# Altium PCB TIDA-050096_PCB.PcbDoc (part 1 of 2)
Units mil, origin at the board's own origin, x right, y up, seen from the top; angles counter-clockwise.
Board outline 3810 x 5470 mil, 4 copper layers (Top Layer, Layer 1, Layer 2, Bottom Layer), stack 70.356 mil thick; 143 components, 52 nets, 310 pads, 92 vias.
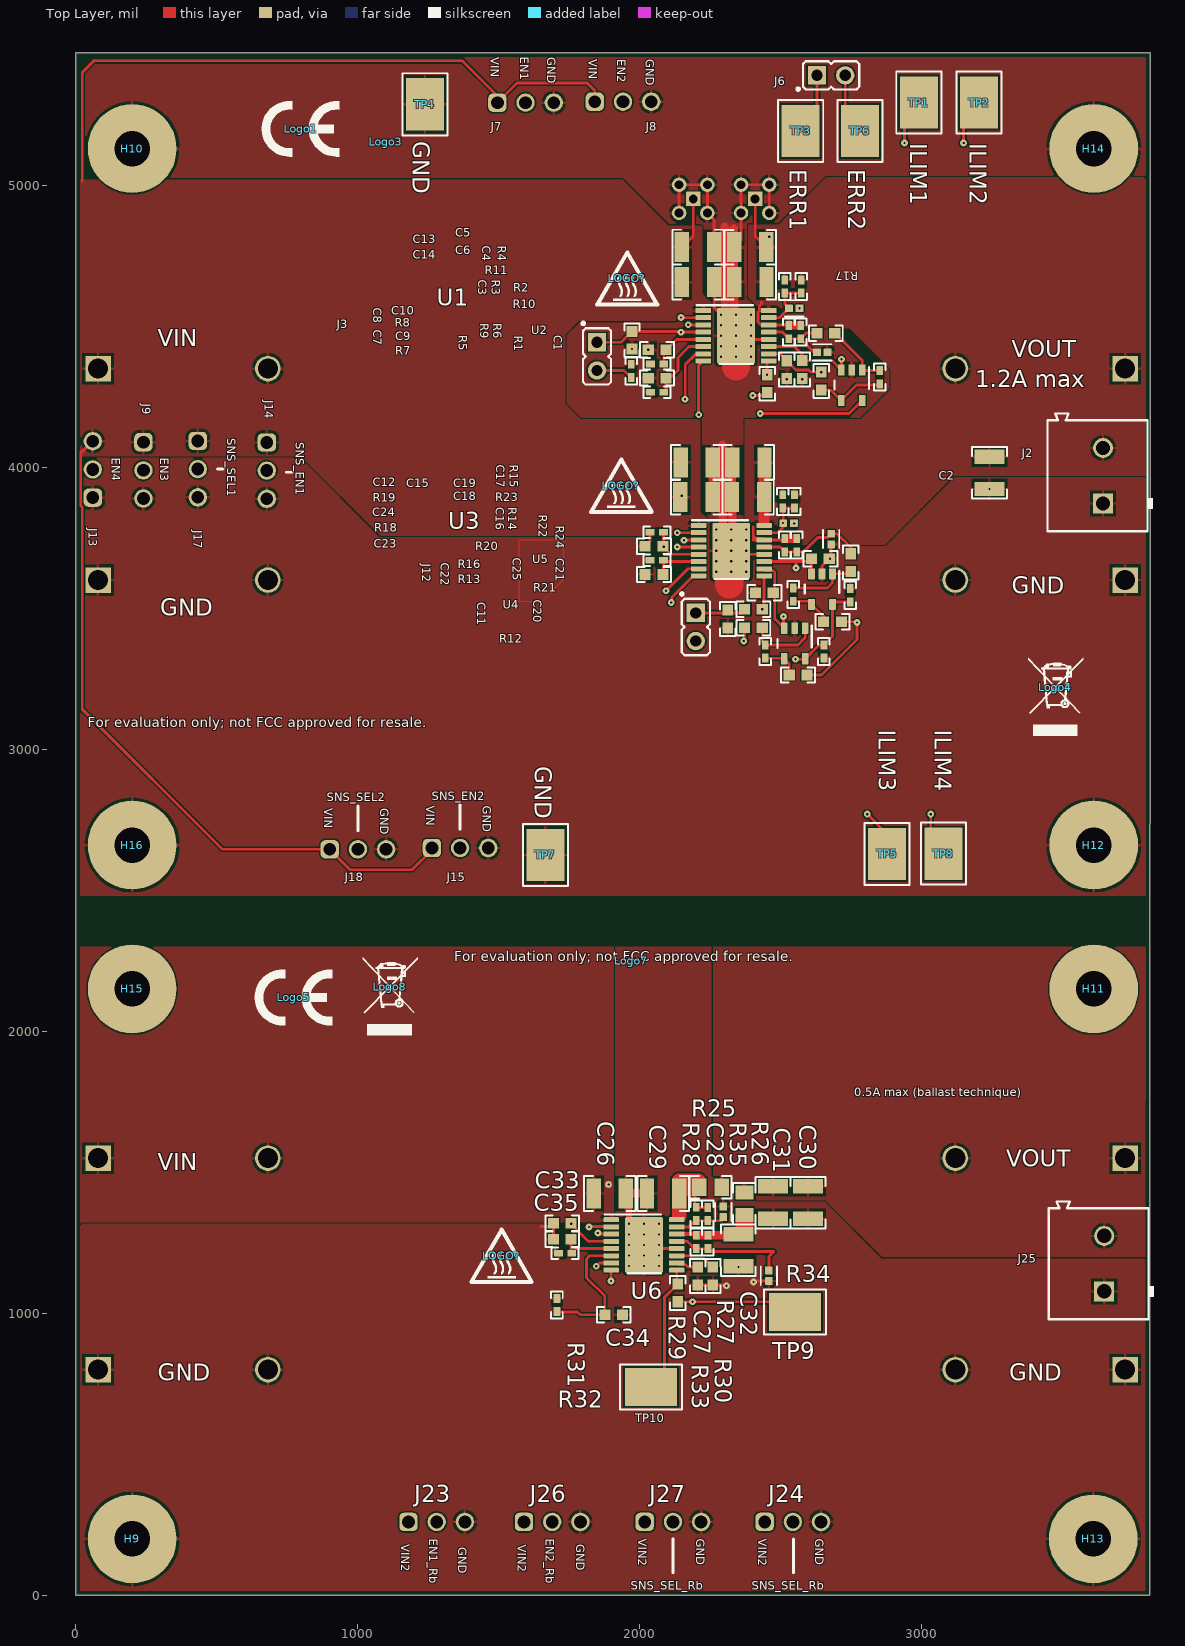
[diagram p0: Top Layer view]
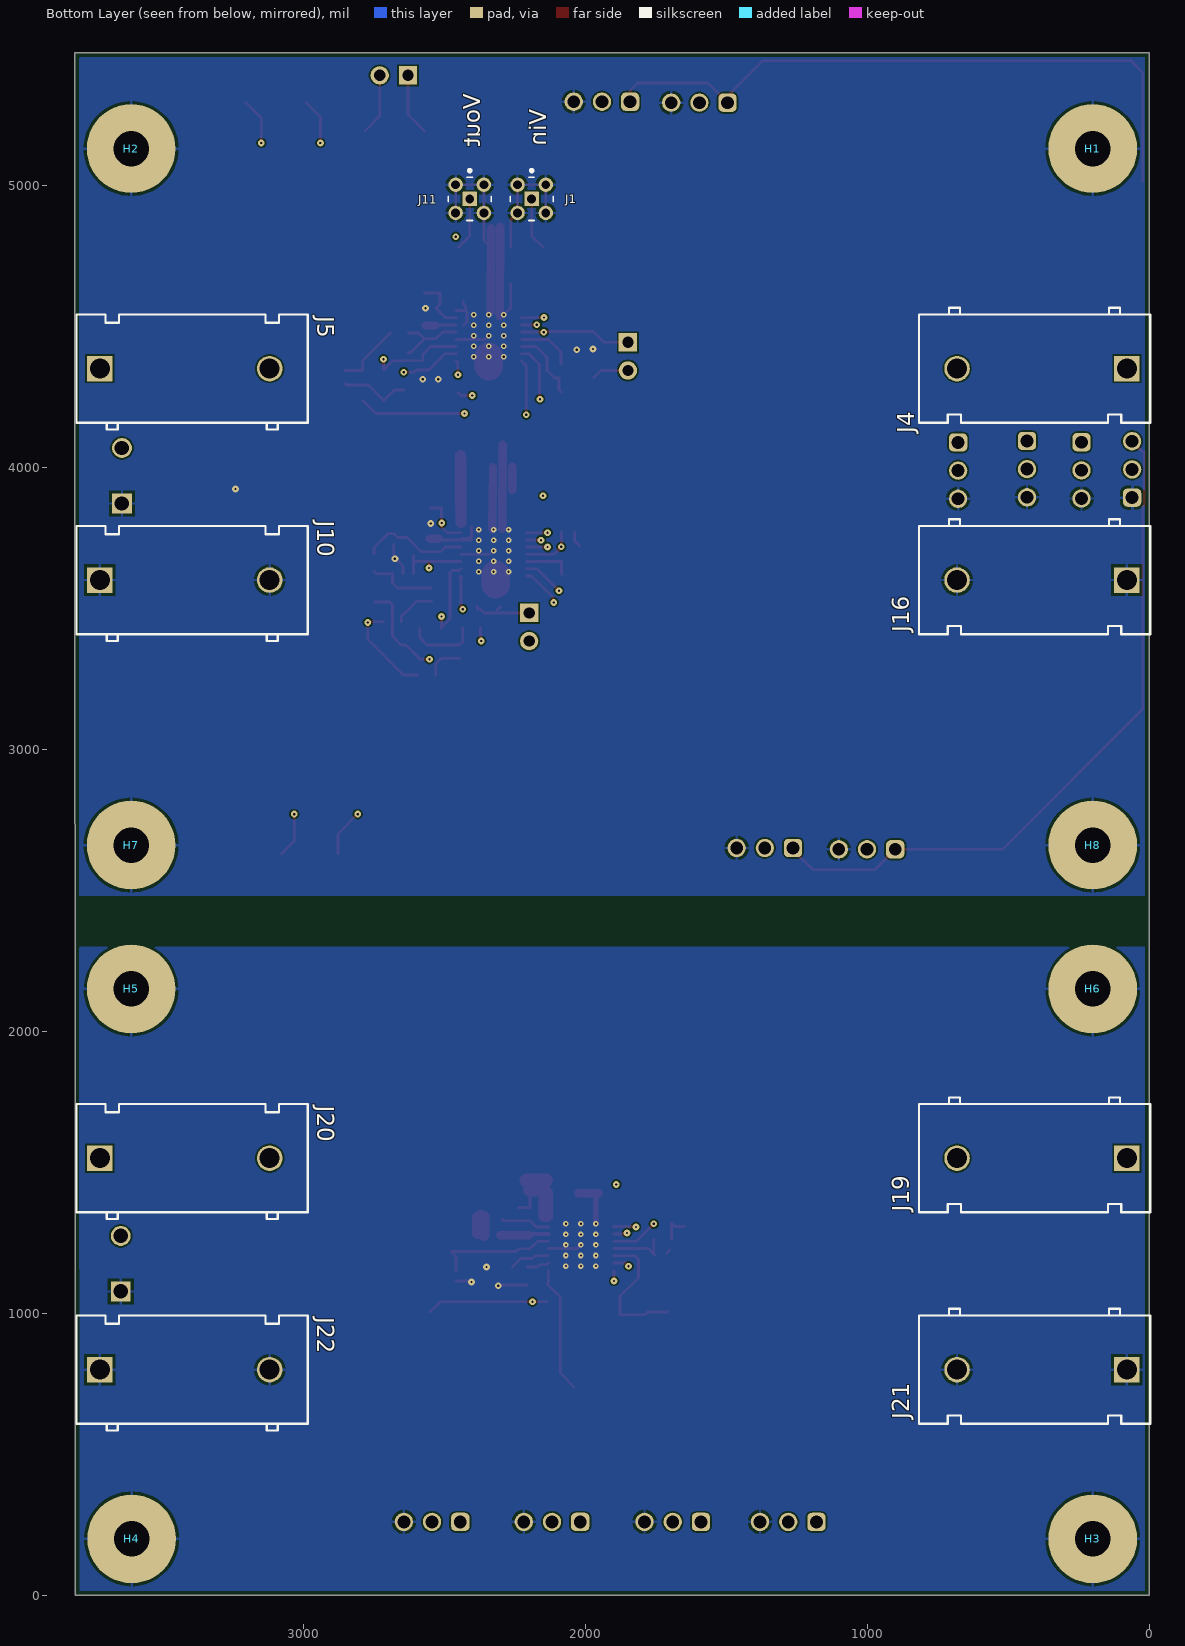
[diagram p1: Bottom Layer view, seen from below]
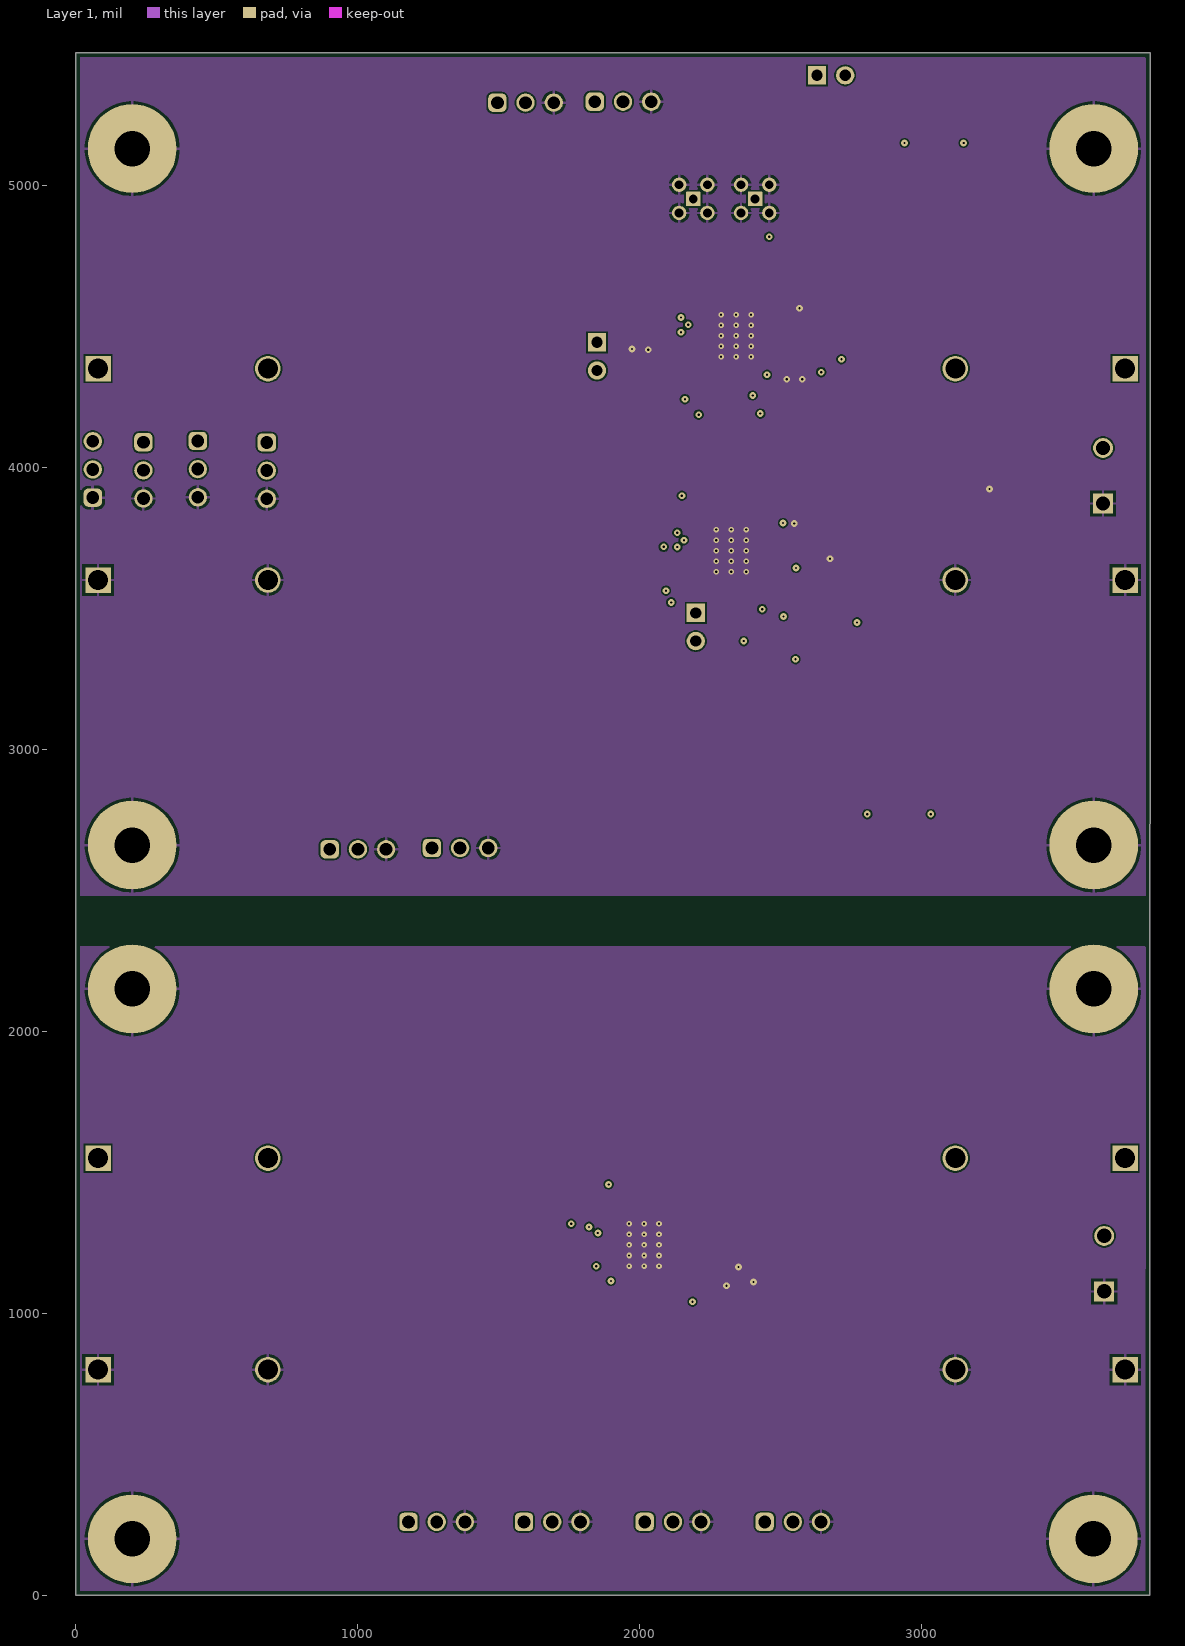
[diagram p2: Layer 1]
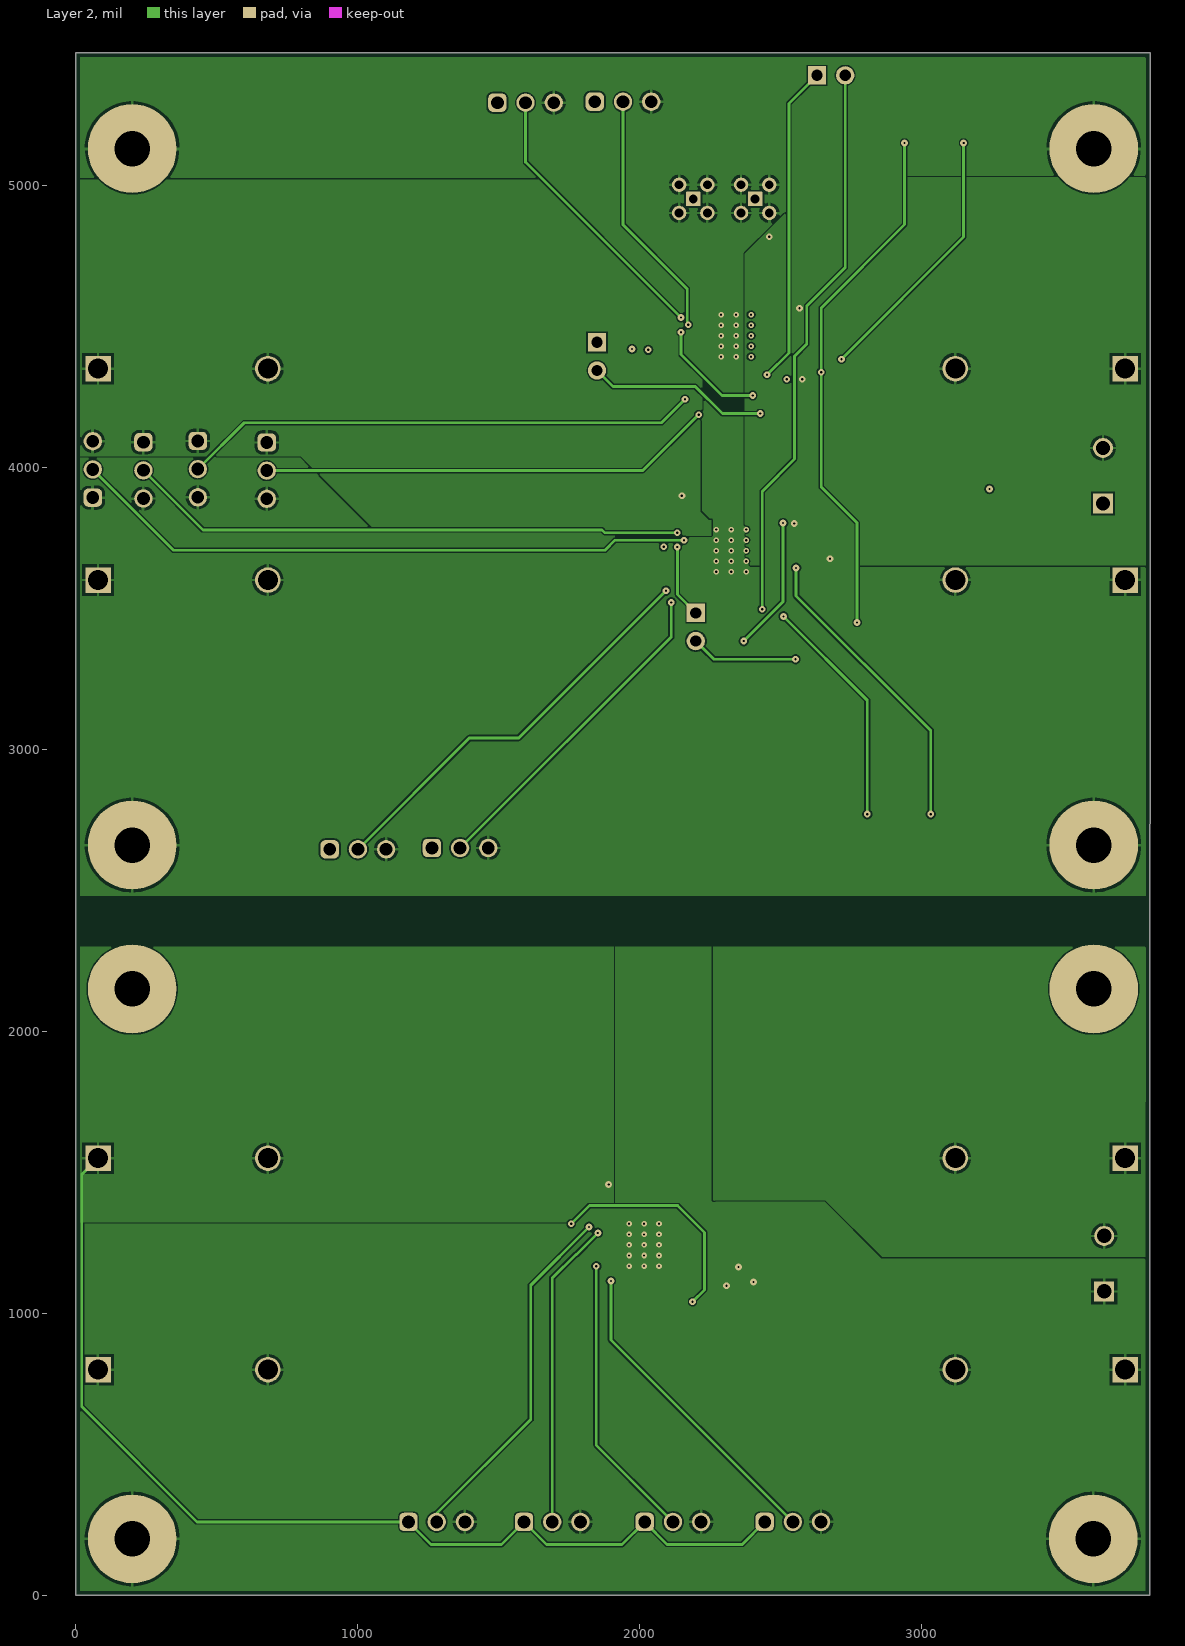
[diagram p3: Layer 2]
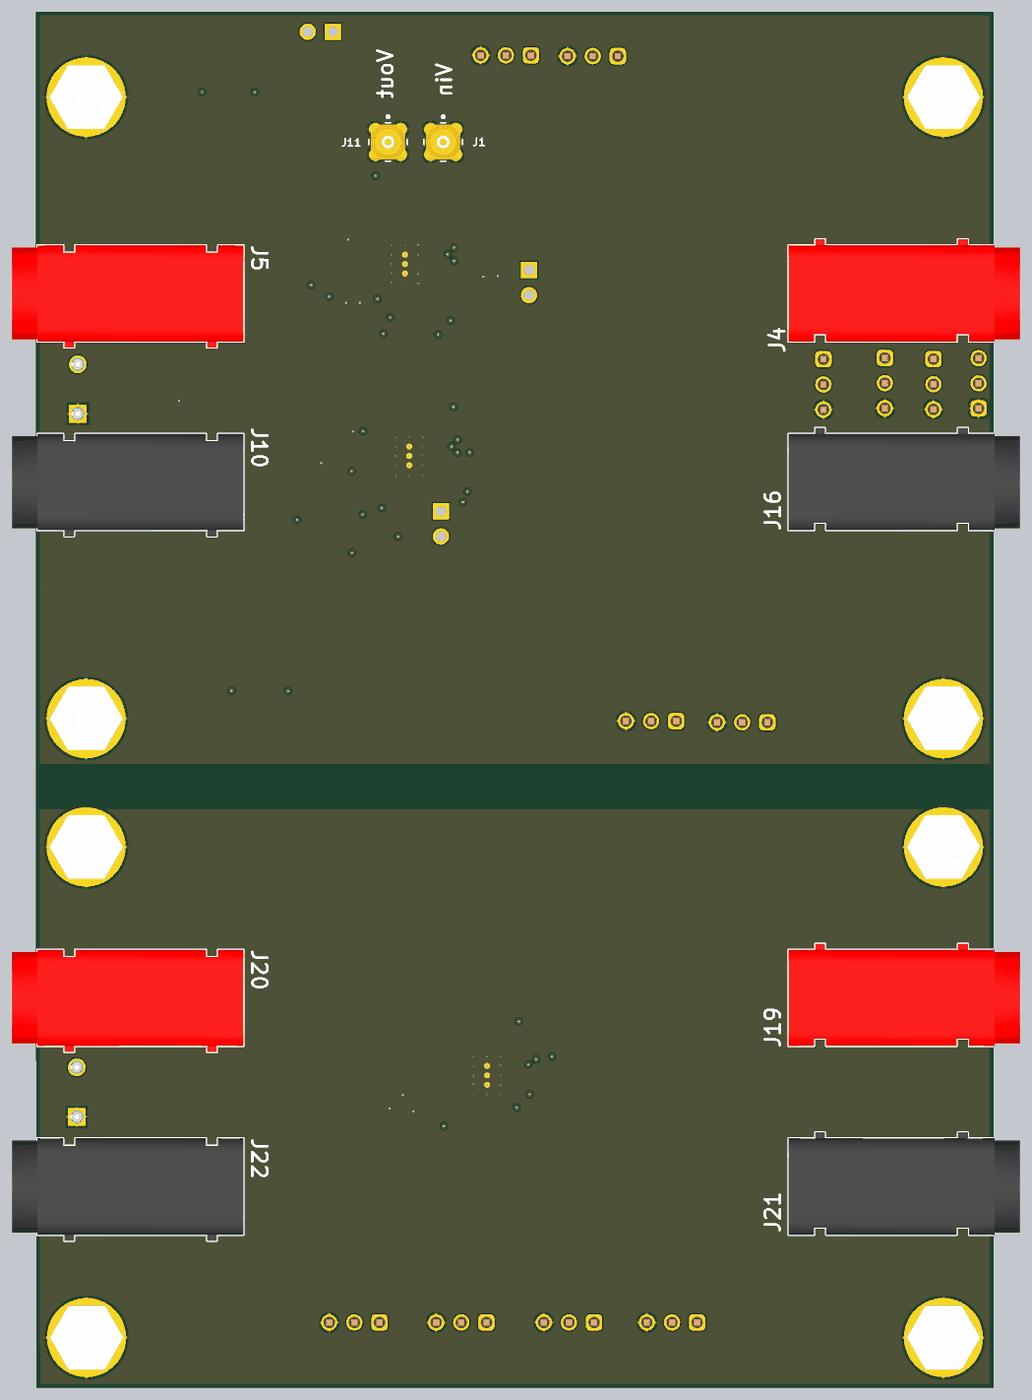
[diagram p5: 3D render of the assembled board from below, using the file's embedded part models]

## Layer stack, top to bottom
Top Solder: solder mask 0.4, Solder Resist, Dk 3.5
Top Layer: signal copper 1.4
Dielectric 1: prepreg 2.8, PP-006, Dk 4.1
Layer 1: signal copper 1.378
Dielectric1: core 59.2, FR-4, Dk 4.8
Layer 2: signal copper 1.378
Dielectric 2: prepreg 2.8, PP-006, Dk 4.1
Bottom Layer: signal copper 1.4
Bottom Solder: solder mask 0.4, Solder Resist, Dk 3.5

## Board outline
0,0 3808.27,0 3810,5470 0,5470

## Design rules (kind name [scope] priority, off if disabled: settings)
AcuteAngle [All] p1: minimum=4.50000000000000E+0001 checktracksonly=FALSE
AssemblyTestPointUsage [All] p1: valid=2
BoardOutlineClearance BoardOutlineClearance_MountingHoles [OnCopper and InComponentClass('Mounting Holes')] p1: gap=40 ignorepadtopadclearanceinfootprint=FALSE
BoardOutlineClearance BoardOutlineClearance_Poly [OnCopper and IsPoly] p2: gap=15 ignorepadtopadclearanceinfootprint=FALSE
BoardOutlineClearance [OnCopper and Not InComponentClass('Logo') and not InComponentClass('FiducialMark') and not InRegion(1000,500,4000,800) and not InPoly] p3: gap=15 ignorepadtopadclearanceinfootprint=FALSE
Clearance Clearance_Keepouts [((IsTrack Or IsArc) And Not InPoly) And IsFree and IsKeepOut vs ((IsTrack Or IsArc) And Not InPoly) And IsFree and IsKeepOut] p1: gap=0 ignorepadtopadclearanceinfootprint=FALSE
Clearance Clearance_Poly [InPolygon] p2: gap=5.63 ignorepadtopadclearanceinfootprint=FALSE except(0: Arc-Hole Track-Hole SMDPad-Hole THPad-Hole Via-Hole Fill-Hole Poly-Hole Region-Hole Text-Hole)
Clearance [Not InComponentClass('FiducialMark')] p3: gap=5.63 ignorepadtopadclearanceinfootprint=TRUE except(0: Arc-Hole Track-Hole SMDPad-Hole THPad-Hole Via-Hole Fill-Hole Poly-Hole Region-Hole Text-Hole)
ComponentClearance ComponentClearance_MountingHoles_FiducialMarks [InComponentClass('Mounting Holes') vs InComponentClass('FiducialMark')] p1: gap=50 collisioncheckmode=3 verticalgap=10 showdistances=FALSE
ComponentClearance ComponentClearance_Shunt [InComponentClass('Header') vs InComponentClass('Shunt')] p2: gap=0 collisioncheckmode=3 verticalgap=0 showdistances=FALSE
ComponentClearance ComponentClearance_NetTie [IsNetTieComponent] p3: gap=0 collisioncheckmode=3 verticalgap=10 showdistances=FALSE
ComponentClearance ComponentClearance_Logo [InComponentClass('Logo')] p4: gap=50 collisioncheckmode=3 verticalgap=10 showdistances=FALSE
ComponentClearance ComponentClearance_ScrewToNut [(HasFootprint('NY PMS 440 0025 PH')) vs (HasFootprint('Keystone_1902C'))] p5: gap=5 collisioncheckmode=3 verticalgap=10 showdistances=FALSE
ComponentClearance ComponentClearance_MountingHoles_Bumpon [InComponentClass('Mounting Holes') vs HasFootprint('Bumpon_SJ5003Transparent')] p6: gap=0 collisioncheckmode=3 verticalgap=0 showdistances=FALSE
ComponentClearance ComponentClearance_MountingHoles [InComponentClass('Mounting Holes')] p7: gap=250 collisioncheckmode=3 verticalgap=100000 showdistances=FALSE
ComponentClearance ComponentClearance_SmallPassives [HasFootprint('0201*') or HasFootprint('0402*') or HasFootprint('0508') or HasFootprint('0603*') or HasFootprint('0612') or HasFootprint('0805*') or HasFootprint('0815*') or HasFootprint('0830*') or HasFootprint('1206*') or HasFootprint('1210*') or HasFootprint('1808*') or HasFootprint('1812*') or HasFootprint('1825*') or HasFootprint('2010*') or HasFootprint('2220*') or HasFootprint('2225*') or HasFootprint('2512*') or HasFootprint('2728*') or HasFootprint('3518*') vs HasFootprint('0201*') or HasFootprint('0402*') or HasFootprint('0508') or HasFootprint('0603*') or HasFootprint('0612') or HasFootprint('0805*') or HasFootprint('0815*') or HasFootprint('0830*') or HasFootprint('1206*') or HasFootprint('1210*') or HasFootprint('1808*') or HasFootprint('1812*') or HasFootprint('1825*') or HasFootprint('2010*') or HasFootprint('2220*') or HasFootprint('2225*') or HasFootprint('2512*') or HasFootprint('2728*') or HasFootprint('3518*')] p8: gap=14.96 collisioncheckmode=3 verticalgap=10 showdistances=FALSE
ComponentClearance ComponentClearance_THtoSMT [IsThruComponent vs IsSMTComponent] p9: gap=40 collisioncheckmode=3 verticalgap=30 showdistances=FALSE
ComponentClearance ComponentClearance_THtoTH [IsThruComponent vs IsThruComponent] p10: gap=30 collisioncheckmode=3 verticalgap=30 showdistances=FALSE
ComponentClearance ComponentClearance_Bumpon [HasFootprint('Keystone_1902C') vs HasFootprint('Bumpon_SJ5003Transparent')] p11: gap=0 collisioncheckmode=3 verticalgap=0 showdistances=FALSE
ComponentClearance [All] p12: gap=30 collisioncheckmode=3 verticalgap=10 showdistances=FALSE
DiffPairsRouting [All] p1: maxlimit=100 minlimit=10 mostfreqgap=10 toplayer_minwidth=15 toplayer_maxwidth=15 toplayer_prefwidth=15 midlayer1_minwidth=15 midlayer1_maxwidth=15 midlayer1_prefwidth=15 midlayer2_minwidth=15 midlayer2_maxwidth=15 midlayer2_prefwidth=15 bottomlayer_minwidth=15 bottomlayer_maxwidth=15 bottomlayer_prefwidth=15 maxuncoupledlength=1000
FabricationTestPointUsage TestPointUsage [All] p1: valid=2 allowmultiple=FALSE
FabricationTestpoint Testpoint [All] p1: side=3 testpointundercomponent=TRUE minsize=40 maxsize=100 preferedsize=60 minholesize=0 maxholesize=40 preferedholesize=32 testpointgrid=1 allowsidetop=TRUE allowsidebottom=TRUE usegrid=TRUE gridtolerance=0.01
FanoutControl Fanout_LCC [IsLCC] p1: bgadir=Out bgaviamode=Centered fanoutstyle=Auto fanoutdirection=Alternating viagrid=1 // Fanout_LCC (Default Rule)
FanoutControl Fanout_BGA [IsBGA] p2: bgadir=Out bgaviamode=Centered fanoutstyle=Auto fanoutdirection=Alternating viagrid=1 // Fanout_BGA (Default Rule)
FanoutControl Fanout_Default [All] p4: bgadir=Out bgaviamode=Centered fanoutstyle=Auto fanoutdirection=Alternating viagrid=1 // Fanout_Default (Default Rule)
FanoutControl Fanout_Small [(CompPinCount < 5)] p5: bgadir=Out bgaviamode=Centered fanoutstyle=Auto fanoutdirection=OutThenIn viagrid=1 // Fanout_Small (Default Rule)
HoleSize [All] p1: absolutevalues=TRUE maxlimit=251 minlimit=6 maxpercent=80.000 minpercent=20.000
HoleToHoleClearance [All] p1: gap=10 allowstackedmicrovias=FALSE
MinimumAnnularRing MinimumAnnularRing_ThermalPadVias [IsVia and InAnyComponent] p1: minimumring=5
MinimumAnnularRing [All] p2: minimumring=5
MinimumSolderMaskSliver MinimumSolderMaskSliver_Logo [InComponentClass('Logo') vs InComponentClass('Logo')] p1: minsoldermaskwidth=0.7
MinimumSolderMaskSliver [All] p2: minsoldermaskwidth=3.94
PlaneConnect [All] p1: planeconnectstyle=Relief reliefexpansion=10 reliefentries=4 reliefconductorwidth=10 reliefairgap=10
PolygonConnect [All] p1: thpad.connectstyle=Relief thpad.reliefconductorwidth=10 thpad.reliefentries=4 thpad.polygonreliefangle="90 Angle" thpad.airgapwidth=10 smdpad.connectstyle=Relief smdpad.reliefconductorwidth=10 smdpad.reliefentries=4 smdpad.polygonreliefangle="90 Angle" smdpad.airgapwidth=10 via.connectstyle=Direct via.reliefconductorwidth=10 via.reliefentries=4 via.polygonreliefangle="90 Angle" via.airgapwidth=10
RoutingVias ThermalPadVias [IsVia and InAnyComponent] p1: holewidth=7 width=15 viastyle="Through Hole" minholewidth=7 minwidth=15 maxholewidth=12.99 maxwidth=23.62
RoutingVias [All] p2: holewidth=7 width=15 viastyle="Through Hole" minholewidth=7 minwidth=15 maxholewidth=40 maxwidth=65
SilkToBoardRegionClearance [Not ((IsComment or IsDesignator) And (Hide <> 'False')) and not InRegion(1000,500,4000,800)] p1:
SilkToSilkClearance SilkToSilkClearance_Pb-FreeLogo [(HasFootprint('Pb-Free_Overlay_Medium') OR HasFootprint('Pb-Free_Overlay_Small')) vs (HasFootprint('Pb-Free_Overlay_Medium') OR HasFootprint('Pb-Free_Overlay_Small'))] p1: silktosilkclearance=0
SilkToSilkClearance [All] p2: silktosilkclearance=4
SilkToSolderMaskClearance SilkToComponentPadClearance [(IsPad or IsFill or IsRegion) and InAnycomponent] p1: minsilkscreentomaskgap=5 clearancetoexposedcopper=TRUE
SilkToSolderMaskClearance "Silk to Solder Mask Opening" [All] p2: minsilkscreentomaskgap=4 clearancetoexposedcopper=FALSE
SolderMaskExpansion [All] p1: expansion=1.97 istentingtop=FALSE
SupplyNets "Schematic Supply Nets_1" [InNet('GND2')] p1: voltage=0.000
SupplyNets "Schematic Supply Nets" [InNet('GND')] p2: voltage=0.000
Width [All] p1: maxlimit=100 minlimit=6 preferedwidth=10 checkconnectedcopper=TRUE
14 further rules are at their usual default settings.

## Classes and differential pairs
component class Parallel_TPS7B7702_Rb_CM_Load: C26 C27 C28 C29 C30 C31 C32 C33 C34 C35 C36 J19 J20 J21 J22 J23 J24 J25 J26 J27 R25 R26 R27 R28 R29 R30 R31 R32 R33 R34 R35 TP9 TP10 U6
component class Header: J3 J6 J7 J8 J9 J12 J13 J14 J15 J17 J18 J23 J24 J26 J27
component class "Mounting Holes": H9 H10 H11 H12 H13 H14 H15 H16
component class Hardware: H1 H2 H3 H4 H5 H6 H7 H8 H9 H10 H11 H12 H13 H14 H15 H16 Logo1 Logo3 Logo4 Logo5 Logo7 Logo8 LOGO? ZZ1 ZZ2 ZZ3 ZZ4 ZZ5
component class AssemblyNote: ZZ1 ZZ2 ZZ3 ZZ4 ZZ5

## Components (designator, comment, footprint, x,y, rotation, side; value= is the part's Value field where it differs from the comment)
C1 "04023C103JAT2A" 0402 2851.59,4319.57 r90 top value=0.01uF
C2 "GRM32ER71H106KA12L" 1210_270 3240,3980 r270 top value=10uF
C3 "04023C103JAT2A" 0402 2528.88,4479.31 r270 top value=0.01uF
C4 "04023C103JAT2A" 0402 2514.67,4641.17 r270 top value=0.01uF
C5 "GRM32ER71H106KA12L" 1210_270 2391.91,4780.44 r180 top value=10uF
C6 "GRM32ER71H106KA12L" 1210_270 2392.29,4656.83 r180 top value=10uF
C7 "C1005X7R1H104K050BE" 0402 1969.44,4341.79 r90 top value=0.1uF
C8 "GRM188R61H105KAALD" 0603 1972.39,4450.61 r90 top value=1uF
C9 "GRM188R61H105KAALD" 0603 2061.59,4316.51 r0 top value=1uF
C10 "GRM188R61H105KAALD" 0603 2061.59,4416.51 r0 top value=1uF
C11 "04023C103JAT2A" 0402 2444.63,3346.65 r90 top value=0.01uF
C12 "GRM32ER71H106KA12L" 1210_270 2201.83,4017.66 r0 top value=10uF
C13 "GRM32ER71H106KA12L" 1210_270 2206.59,4780.71 r0 top value=10uF
C14 "GRM32ER71H106KA12L" 1210_270 2206.59,4656.51 r0 top value=10uF
C15 "GRM32ER71H106KA12L" 1210_270 2201.38,3893.96 r0 top value=10uF
C16 "04023C103JAT2A" 0402 2513.56,3723.85 r270 top value=0.01uF
C17 "04023C103JAT2A" 0402 2507.47,3879.2 r270 top value=0.01uF
C18 "GRM32ER71H106KA12L" 1210_270 2385.14,4017.66 r180 top value=10uF
C19 "GRM32ER71H106KA12L" 1210_270 2383.95,3893.89 r180 top value=10uF
C20 "C1005X7R1H104K050BE" 0402 2653.07,3346.67 r270 top value=0.1uF
C21 "C1005X7R1H104K050BE" 0402 2746.41,3546.28 r90 top value=0.1uF
C22 "GRM188R61H105KAALD" 0603 2312.39,3462.15 r270 top value=1uF
C23 "GRM188R61H105KAALD" 0603 2050.45,3619.79 r0 top value=1uF
C24 "GRM188R61H105KAALD" 0603 2050.45,3719.79 r0 top value=1uF
C25 "04023C103JAT2A" 0402 2544.49,3548.38 r90 top value=0.01uF
C26 "GRM32ER71H106KA12L" 1210_270 1893.88,1424.91 r0 top value=10uF
C27 "04023C103JAT2A" 0402 2200.44,1253.07 r270 top value=0.01uF
C28 "04023C103JAT2A" 0402 2241.51,1351.94 r270 top value=0.01uF
C29 "GRM32ER71H106KA12L" 1210_270 2082.82,1424.59 r180 top value=10uF
C30 "GRM32ER71H106KA12L" 1210_270 2596.27,1392.54 r270 top value=10uF
C31 "GRM32ER71H106KA12L" 1210_270 2472.83,1392.54 r270 top value=10uF
C32 "GRM32ER71H106KA12L" 1210_270 2349.4,1223.11 r270 top value=10uF
C33 "GRM188R61H105KAALD" 0603 1725.12,1319.5 r180 top value=1uF
C34 "GRM188R61H105KAALD" 0603 1907.59,994.33 r180 top value=1uF
C35 "GRM188R61H105KAALD" 0603 1725.09,1262.19 r0 top value=1uF
H1 "1902C" Keystone_1902C 200,5130 r180 bottom locked
H2 "1902C" Keystone_1902C 3610,5130 r180 bottom locked
H3 "1902C" Keystone_1902C 200,200 r180 bottom locked
H4 "1902C" Keystone_1902C 3608.27,200 r180 bottom locked
H5 "1902C" Keystone_1902C 3610,2150 r180 bottom
H6 "1902C" Keystone_1902C 200,2150 r180 bottom
H7 "1902C" Keystone_1902C 3610,2660 r180 bottom
H8 "1902C" Keystone_1902C 200,2660 r180 bottom
H9 "NY PMS 440 0025 PH" "NY PMS 440 0025 PH" 200,200 r0 top locked
H10 "NY PMS 440 0025 PH" "NY PMS 440 0025 PH" 200,5130 r0 top locked
H11 "NY PMS 440 0025 PH" "NY PMS 440 0025 PH" 3610,2150 r0 top
H12 "NY PMS 440 0025 PH" "NY PMS 440 0025 PH" 3610,2660 r0 top
H13 "NY PMS 440 0025 PH" "NY PMS 440 0025 PH" 3608.27,200 r0 top locked
H14 "NY PMS 440 0025 PH" "NY PMS 440 0025 PH" 3610,5130 r0 top locked
H15 "NY PMS 440 0025 PH" "NY PMS 440 0025 PH" 200,2150 r0 top
H16 "NY PMS 440 0025 PH" "NY PMS 440 0025 PH" 200,2660 r0 top
J1 "RF12-07H-T-00-50-G" FP-RF12-07H-T-00-50-G_CONN_MMCX-MFG 2409.22,4951.97 r270 bottom
J2 "691 101 710 002" Wurth_691101710002 3642.74,3970 r90 top
J3 "PBC02SAAN" Sullins_PBC02SAAN 1848.44,4393.21 r0 top
J4 "571-0500" 571-0500 380,4350 r0 bottom
J5 "571-0500" 571-0500 3420,4350 r180 bottom
J6 "PBC02SAAN" Sullins_PBC02SAAN 2678.54,5390 r90 top
J7 "61300311121" WURTH_61300311121 1595,5293.09 r0 top
J8 "61300311121" WURTH_61300311121 1940.57,5296.49 r0 top
J9 "61300311121" WURTH_61300311121 239.68,3989.1 r270 top
J10 "571-0100" 571-0100 3420,3600 r180 bottom
J11 "RF12-07H-T-00-50-G" FP-RF12-07H-T-00-50-G_CONN_MMCX-MFG 2189.66,4951.97 r270 bottom
J12 "PBC02SAAN" Sullins_PBC02SAAN 2198.61,3433.65 r0 top
J13 "61300311121" WURTH_61300311121 60.33,3992.49 r90 top
J14 "61300311121" WURTH_61300311121 677.35,3988.19 r270 top
J15 "61300311121" WURTH_61300311121 1362.81,2650.02 r0 top
J16 "571-0100" 571-0100 380,3600 r0 bottom
J17 "61300311121" WURTH_61300311121 432.84,3993.49 r270 top
J18 "61300311121" WURTH_61300311121 1000.42,2645.17 r0 top
J19 "571-0500" 571-0500 380,1550 r0 bottom
J20 "571-0500" 571-0500 3420,1550 r180 bottom
J21 "571-0100" 571-0100 380,800 r0 bottom
J22 "571-0100" 571-0100 3420,800 r180 bottom
J23 "61300311121" WURTH_61300311121 1279.75,260 r0 top
J24 "61300311121" WURTH_61300311121 2542.93,260 r0 top
J25 "691 101 710 002" Wurth_691101710002 3646.99,1175.73 r90 top
J26 "61300311121" WURTH_61300311121 1689.47,260 r0 top
J27 "61300311121" WURTH_61300311121 2117.53,260 r0 top
Logo1 "CE Mark" CE_Mark_5mm 797.27,5200.04 r0 top
Logo3 "FCC disclaimer" FCC_disclaimer 1100,5155.19 r0 top
Logo4 "WEEE logo" WEEE_Minimum 3473.45,3220 r0 top
Logo5 "CE Mark" CE_Mark_5mm 772.4,2119.79 r0 top
Logo7 "FCC disclaimer" FCC_disclaimer 1970,2250 r0 top
Logo8 "WEEE logo" WEEE_Minimum 1112.72,2157.99 r0 top
LOGO? "CAUTION HOT SURFACE" IEC_HotSurface_Small 1510,1203.85 r0 top
LOGO? "CAUTION HOT SURFACE" IEC_HotSurface_Small 1934.78,3935.07 r0 top
LOGO? "CAUTION HOT SURFACE" IEC_HotSurface_Small 1955.78,4669.8 r0 top
R1 "RC0603FR-0710KL" 0603 2643.34,4305.79 r270 top value=10.0k
R2 "RC0603FR-07787RL" 0603 2659.84,4475.76 r180 top value=787
R3 "CRCW04027K15FKED" 0402 2570.36,4479.31 r270 top value=7.15k
R4 "CRCW04027K15FKED" 0402 2572.09,4641.17 r270 top value=7.15k
R5 "RC0603FR-0710KL" 0603 2451.59,4296.51 r90 top value=10.0k
R6 "RC0603FR-07787RL" 0603 2576.14,4346.65 r90 top value=787
R7 "CRCW0402732RFKED" 0402 2061.59,4266.51 r0 top value=732
R8 "CRCW0402732RFKED" 0402 2061.59,4366.51 r0 top value=732
R9 "RC0603FR-07787RL" 0603 2521.59,4346.51 r90 top value=787
R10 "RC0402FR-071KL" FP-RC0402FR-071KL_0402-IPC_A 2647.18,4407.46 r180 top value=1k
R11 "RC0402FR-071KL" FP-RC0402FR-071KL_0402-IPC_A 2547.72,4563.86 r180 top value=1k
R12 "RC0603FR-0710KL" 0603 2561.47,3263.45 r180 top value=10.0k
R13 "RC0603FR-07787RL" 0603 2402.69,3431.17 r180 top value=787
R14 "CRCW04027K15FKED" 0402 2556.49,3723.85 r270 top value=7.15k
R15 "CRCW04027K15FKED" 0402 2548.75,3879.2 r270 top value=7.15k
R16 "RC0603FR-0710KL" 0603 2402.69,3496.8 r0 top value=10.0k
R17 "RC0603FR-07787RL" 0603 2640.41,3675.85 r180 top value=787
R18 "CRCW0402732RFKED" 0402 2060.45,3669.79 r0 top value=732
R19 "CRCW0402732RFKED" 0402 2060.45,3769.79 r0 top value=732
R20 "RC0603FR-07787RL" 0603 2441.79,3555.46 r0 top value=787
R21 "RC0603FR-0710KL" 0603 2683.72,3452.35 r180 top value=10.0k
R22 "RC0402FR-071KL" FP-RC0402FR-071KL_0402-IPC_A 2678.54,3745.56 r90 top value=1k
R23 "RC0402FR-071KL" FP-RC0402FR-071KL_0402-IPC_A 2527.57,3801.76 r180 top value=1k
R24 "RC0603FR-07787RL" 0603 2748.75,3662.04 r90 top value=787
R25 "RC0805FR-071R33L" 0805_HV 2250.87,1446.94 r0 top value=1.33
R26 "RC0805FR-071R33L" 0805_HV 2371.02,1388.41 r90 top value=1.33
R27 "CRCW04027K15FKED" 0402 2241.76,1252.96 r270 top value=7.15k
R28 "CRCW04027K15FKED" 0402 2200.15,1352.05 r270 top value=7.15k
R29 "RC0603FR-0710KL" 0603 2135.09,1072.19 r90 top value=10.0k
R30 "RC0603FR-07787RL" 0603 2259.56,1132.29 r90 top value=787
R31 "CRCW0402732RFKED" 0402 1706.39,1029.17 r270 top value=732
R32 "CRCW0402732RFKED" 0402 1735.09,1212.19 r0 top value=732
R33 "RC0603FR-07787RL" 0603 2205.09,1132.19 r90 top value=787
R34 "RC0402FR-071KL" FP-RC0402FR-071KL_0402-IPC_A 2457.86,1133.21 r90 top value=1k
R35 "RC0402FR-071KL" FP-RC0402FR-071KL_0402-IPC_A 2296.17,1359.5 r270 top value=1k
TP1 "5016" Testpoint_Keystone_Compact 2989.51,5293.15 r90 top
TP2 "5016" Testpoint_Keystone_Compact 3203.19,5293.15 r270 top
TP3 "5016" Testpoint_Keystone_Compact 2570.64,5193.15 r90 top
TP4 "5016" Testpoint_Keystone_Compact 1238.14,5287.43 r90 top
TP5 "5016" Testpoint_Keystone_Compact 2876.88,2628.63 r270 top
TP6 "5016" Testpoint_Keystone_Compact 2780.64,5193.15 r270 top
TP7 "5016" Testpoint_Keystone_Compact 1665.27,2625.17 r90 top
TP8 "5016" Testpoint_Keystone_Compact 3076.88,2629.73 r90 top
TP9 "5016" Testpoint_Keystone_Compact 2550,1004.17 r0 top
TP10 "5016" Testpoint_Keystone_Compact 2039.58,738.95 r0 top
U1 "TPS7B7702QPWPRQ1" PWP0016J_N 2341.59,4466.51 r0 top
U2 "OPA388IDBVR" DBV0005A_N 2751.59,4291.53 r270 top
U3 "TPS7B7702QPWPRQ1" PWP0016J_N 2324.58,3704.16 r0 top
U4 "OPA388IDBVR" DBV0005A_N 2549.19,3375.14 r270 top
U5 "OPA388IDBVR" DBV0005A_N 2646.32,3568.07 r270 top
U6 "TPS7B7702QPWPRQ1" PWP0016J_N 2015.09,1242.19 r0 top
ZZ1 "This Assembly Note is for PCB labels only" AssemblyNoteLabel -395.71,7825.79 r0 top
ZZ2 "These assemblies are ESD sensitive, ESD precautions shall be observed." AssemblyNote -395.71,7716.91 r0 top
ZZ3 "These assemblies must be clean and free from flux and all contaminants. Use of no clean flux is not acceptable." AssemblyNote -395.71,7628.35 r0 top
ZZ4 "These assemblies must comply with workmanship standards IPC-A-610 Class 2, unless otherwise specified." AssemblyNote -395.71,7539.8 r0 top
ZZ5 "The tab route width shall be between 80 mils and 120 mils" AssemblyNote -400,7440 r0 top

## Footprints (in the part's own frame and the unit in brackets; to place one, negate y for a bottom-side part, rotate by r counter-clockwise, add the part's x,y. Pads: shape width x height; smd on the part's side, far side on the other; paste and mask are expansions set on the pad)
0402 [mm] "0402 from SM-752 data"
  rect 0.8x0.6 smd: 1(-0.6,0) 2(0.6,0)
  silkscreen extent -1.22,-0.52 1.22,0.52, body extent -0.55,-0.3 0.55,0.3, height 0.6
571-0100 [mm] "Deltron Emcon recommended land pattern 2003-10-13"
  rect 2.3x2.3 hole 1.8: 1(-7.65,0)
  round 2.3 hole 1.8: 2(7.65,0)
  silkscreen extent -9.74,-5.47 11.09,4.88, body extent -12.28,-5.47 11.09,4.88, height 12.41
571-0500 [mm] "Deltron Emcon recommended land pattern 2003-10-13"
  rect 2.3x2.3 hole 1.8: 1(-7.65,0)
  round 2.3 hole 1.8: 2(7.65,0)
  silkscreen extent -9.74,-5.47 11.09,4.88, body extent -12.28,-5.47 11.09,4.88, height 12.41
0603 [mm] "0603 from SM-752 data"
  rect 1x0.95 smd: 1(-0.8,0) 2(0.8,0)
  silkscreen extent -1.52,-0.69 1.52,0.69, body extent -0.87,-0.47 0.87,0.47, height 1
0805_HV [mil] "0805 with 30mil clearance between pads"
  rect 50x63 smd: 1(-40,0) 2(40,0)
  silkscreen extent -74,-40 74,40, body extent -43,-29 43,29, height 57
1210_270 [mm] "1210"
  rect 1.3x2.7 smd: 1(-1.45,0) 2(1.45,0)
  silkscreen extent -2.32,-1.57 2.32,1.57, body extent -1.7,-1.35 1.7,1.35, height 2.7
AssemblyNote [mil] "Assembly Note"
AssemblyNoteLabel [mil] "Assembly Note for PCB Labels"
CE_Mark_5mm [mil] "Minimum text height for CE Mark"
  silkscreen extent -138,-98 138,98
DBV0005A_N [mm] "SOT23, 5-Leads, Body 2.9x1.6mm, Pitch 0.95mm, Lead Span 2.8mm, IPC Medium Density"
  rrect17% 1x0.6 smd: 1(-1.375,0.95) 2(-1.375,0) 3(-1.375,-0.95) 4(1.375,-0.95) 5(1.375,0.95)
  silkscreen extent -1.63,-1.55 0.38,1.55, body extent -1.42,-1.46 1.42,1.46, height 1.09
FCC_disclaimer [mil]
FP-RC0402FR-071KL_0402-IPC_A [mil]
  rrect15% 28.16x26.48 smd paste+0 mask+0: 1(-18.84,0) 2(18.84,0)
  silkscreen extent -33,-29 33,29, body extent -41,-21 41,21, height 10
FP-RF12-07H-T-00-50-G_CONN_MMCX-MFG [mm]
  rrect8% 1.3x1.3 hole 0.8 paste-2539.97 mask+0: 1(0,0)
  round 1.3 hole 0.8 paste-2539.97 mask+0: 2(-1.27,1.27) 3(1.27,1.27) 4(-1.27,-1.27) 5(1.27,-1.27)
  silkscreen extent -2.67,-1.94 1.94,1.94, body extent -1.75,-1.75 1.75,1.75, height 5.26
IEC_HotSurface_Small [mil]
  silkscreen extent -107,-93 107,92
Keystone_1902C [mil] "Hex Standoff, 4-40 threaded, nylon"
  round 1 on Mech4: 0(0,0)
  body extent -145,-126 146,126, height 501
"NY PMS 440 0025 PH" [mm] "4-40 nylon screw and mounting hole"
  round 8 hole 3.2: 1(0,0)
  body extent -3.3,-3.3 3.3,3.3, height 2.69
PWP0016J_N [mm] "TSOP, 16-Leads, Body 5x4.4mm, Pitch 0.65mm, Exposed Pad, IPC Medium Density"
  rrect22% 1.4x0.45 smd: 1(-2.95,2.275) 2(-2.95,1.625) 3(-2.95,0.975) 4(-2.95,0.325) 5(-2.95,-0.325) 6(-2.95,-0.975) 7(-2.95,-1.625) 8(-2.95,-2.275) 9(2.95,-2.275) 10(2.95,-1.625) 11(2.95,-0.975) 12(2.95,-0.325) 13(2.95,0.325) 14(2.95,0.975) 15(2.95,1.625) 16(2.95,2.275)
  rrect6% 3.4x5 smd paste-1.7 mask-1.7: 17(0,0)
  rrect4% 2.46x3.55 on Top Solder: 17(0,0)
  rrect4% 2.46x3.55 on Top Paste: 17(0,0)
  silkscreen extent -3.55,-2.55 1.5,2.75, body extent -3.2,-2.5 3.2,2.5, height 1.13
Sullins_PBC02SAAN [mm] "Sullins 100mil, 1x2, 230 mil above insulator"
  rect 1.65x1.65 hole 1.016: 1(0,1.27)
  round 1.65 hole 1.016: 2(0,-1.27)
  silkscreen extent -1.37,-2.54 1.27,3.1, body extent -1.27,-2.54 1.27,2.54, height 8.38
Testpoint_Keystone_Compact [mil] "Compact SMT test point"
  rect 185x135 smd: 1(0,0)
  silkscreen extent -110,-80 110,80, body extent -75,-56 75,56, height 91
WEEE_Minimum [mil] "WEEElie bin"
  silkscreen extent -95,-172 99,104
WURTH_61300311121 [mm] "Header, 2.54mm, 3x1, TH"
  rrect50% 1.65x1.65 hole 1.15: 1(-2.54,0)
  round 1.65 hole 1.15: 2(0,0) 3(2.54,0)
  body extent -3.81,-1.27 3.81,1.27, height 8.54
Wurth_691101710002 [mm] "Terminal Block, 5 mm, 2x1, TH"
  rect 1.8x1.8 hole 1.3: 1(-2.5,0)
  round 1.8 hole 1.3: 2(2.5,0)
  silkscreen extent -5,-4.5 5.6,5, body extent -5.6,-4 5.6,5, height 12.5

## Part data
C1 C3 C4 C11 C16 C17 C25 C27 C28: library part CMP-0085568-1, "CAP, CERM, 0.01 µF, 25 V,+/- 5%, X7R, 0402", Cap_Case=0402, Manufacturer=AVX, TempCo=X7R, Tolerance_%=5%, Value2=25V, ValueDisplayed=0.01µF
C2 C5 C6 C12 C13 C14 C15 C18 C19 C26 C29 C30 C31 C32: library part CMP-0009226-3, "CAP, CERM, 10 uF, 50 V, +/- 10%, X7R, 1210", Cap_Case=1210, Manufacturer=MuRata, Supplier Part Number 1=490-6544-1-ND, TempCo=X7R, Tolerance_%=10%, Value1=Unknown, Value2=50V, ValueDisplayed=10uF
C7 C20 C21: library part CMP-0064946-2, "CAP, CERM, 0.1 uF, 50 V,+/- 10%, X7R, 0402", Cap_Case=0402, Manufacturer=TDK, Supplier Part Number 1=445-173610-1-ND, TempCo=X7R, Tolerance_%=10%, Value1=Unknown, Value2=50V, ValueDisplayed=0.1uF
C8 C9 C10 C22 C23 C24 C33 C34 C35: library part CMP-0007350-6, "CAP, CERM, 1 uF, 50 V, +/- 10%, X5R, 0603", Cap_Case=0603, Manufacturer=MuRata, Supplier Part Number 1=13T1194, TempCo=X5R, Tolerance_%=10%, Value1=Unknown, Value2=50V, ValueDisplayed=1uF
H1 H2 H3 H4 H5 H6 H7 H8: library part CMP-0003610-1, "Standoff, Hex, 0.5\"L #4-40 Nylon", Manufacturer=Keystone, Supplier Part Number 1=36-1902C-ND
H9 H10 H11 H12 H13 H14 H15 H16: library part CMP-0003617-1, "Machine Screw, Round, #4-40 x 1/4, Nylon, Philips panhead", Manufacturer="B&F Fastener Supply", Supplier Part Number 1=H542-ND
J1 J11: library part CMP-0096285-1, "MMCX Connector Jack, Female Socket 50Ohm Through Hole Solder", Dielectric Material=TEFLON, Digikey Part Number=2057-RF12-07H-T-00-50-G-ND, Manufacturer="Adam Tech", Operating Temperature Range=to
J2 J25: library part CMP-0054828-1, "Terminal Block, 5 mm, 2x1, Tin, TH", Manufacturer="Wurth Elektronik", Supplier Part Number 1=732-2026-ND
J3 J6 J12: library part CMP-0054566-1, "Header, 100mil, 2x1, Gold, TH", Color=Black, Current_A=3A, Manufacturer="Sullins Connector Solutions", Supplier Part Number 1=S1011E-02-ND, Voltage_V=1.8kV
J4 J5 J19 J20: library part CMP-0055393-3, "Standard Banana Jack, insulated, 10A, red", Manufacturer="DEM Manufacturing", Supplier Part Number 1=30M0087
J7 J8 J9 J13 J14 J15 J17 J18 J23 J24 J26 J27: library part CMP-0054796-4, "Header, 2.54 mm, 3x1, Gold, TH", Manufacturer="Wurth Elektronik", Supplier Part Number 1=732-5316-ND
J10 J16 J21 J22: library part CMP-0055389-3, "Standard Banana Jack, insulated, 10A, black", Manufacturer="DEM Manufacturing", Supplier Part Number 1=45M6896
Logo1 Logo5: library part CMP-0074844-1
Logo3 Logo7: library part CMP-0074847-1, "FCC_disclaimer"
Logo4 Logo8: library part CMP-0074769-1
LOGO? LOGO? LOGO?: library part CMP-0074837-1, "IEC 61010-1 Hot Surface Warning"
R1 R5 R12 R16 R21 R29: library part CMP-0022746-5, "RES, 10.0 k, 1%, 0.1 W, 0603", Manufacturer=Yageo, Power_W=100mW, Supplier Part Number 1=311-10.0KHRCT-ND, TempCo="100 ppm/C", Tolerance_%=1%, Value2=0.1W, Value_Code=10k0, ValueDisplayed=10.0k
R2 R6 R9 R13 R17 R20 R24 R30 R33: library part CMP-0023274-5, "RES, 787, 1%, 0.1 W, 0603", Manufacturer=Yageo, Power_W=100mW, Supplier Part Number 1=311-787HRCT-ND, TempCo="100 ppm/C", Tolerance_%=1%, Value2=0.1W, Value_Code=787R, ValueDisplayed=787
R3 R4 R14 R15 R27 R28: library part CMP-0026553-2, "RES, 7.15 k, 1%, 0.063 W, AEC-Q200 Grade 0, 0402", Manufacturer=Vishay-Dale, Power_W=63mW, Supplier Part Number 1=541-7.15KLCT-ND, TempCo="100 ppm/C", Tolerance_%=1%, Value2=0.063W, Value_Code=7k15, ValueDisplayed=7.15k
R7 R8 R18 R19 R31 R32: library part CMP-0026538-2, "RES, 732, 1%, 0.063 W, AEC-Q200 Grade 0, 0402", Manufacturer=Vishay-Dale, Power_W=63mW, Supplier Part Number 1=541-732LCT-ND, TempCo="100 ppm/C", Tolerance_%=1%, Value2=0.063W, Value_Code=732R, ValueDisplayed=732
R10 R11 R22 R23 R34 R35: library part CMP-0098279-1, "RES Thick Film SMD 1kΩ 1% 1/16W 0402 100ppm/°C", Digikey Part Number=311-1.00KLRCT-ND, Manufacturer=Yageo, Mouser Part Number=603-RC0402FR-071KL, Operating Temperature Range="-55°C to +155°C", Power_W=63mW, TempCo=100ppm/°C, Tolerance_%=1%
R25 R26: library part CMP-0021875-2, "RES, 1.33, 1%, 0.125 W, 0805", Manufacturer="Yageo America", Power_W=125mW, Supplier Part Number 1=311-1.33CRCT-ND, TempCo="200 ppm/C", Tolerance_%=1%, Value2=0.125W, Value_Code=1R33, ValueDisplayed=1.33
TP1 TP2 TP3 TP4 TP5 TP6 TP7 TP8 TP9 TP10: library part CMP-0055153-1, "Test Point, Compact, SMT", Manufacturer=Keystone, Supplier Part Number 1=36-5016TR-ND
U1 U3 U6: library part CMP-0073734-2, "Dual-Channel Antenna LDO With Current Sense, PWP0016J (TSSOP-16)", Alternate Manufacturer="Texas Instruments"
U2 U4 U5: library part CMP-0860922-1, "10MHz, CMOS, Zero-Drift, Zero-Crossover, True RRIO Precision Operational Amplifier, DBV0005A (SOT-23-5)", Alternate Manufacturer="Texas Instruments", Alternate PartNumber=OPA388IDBVT, Operating Temperature Range="-40 to 125 C", Rating=Catalog
ZZ1: library part CMP-0003616-3
ZZ2: library part CMP-0077236-1
ZZ3: library part CMP-0077237-1
ZZ4: library part CMP-0077238-1
ZZ5: library part CMP-0077238-1, "These assemblies must comply with workmanship standards IPC-A-610 Class 2, unless otherwise specified."

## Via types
v1: diameter 24, hole 8, Top Layer to Bottom Layer, tented both sides, 47 vias
v2: diameter 19.68, hole 7.87, Top Layer to Bottom Layer, tented both sides, 36 vias
v3: diameter 19.68, hole 7.87, Top Layer to Bottom Layer, 9 vias

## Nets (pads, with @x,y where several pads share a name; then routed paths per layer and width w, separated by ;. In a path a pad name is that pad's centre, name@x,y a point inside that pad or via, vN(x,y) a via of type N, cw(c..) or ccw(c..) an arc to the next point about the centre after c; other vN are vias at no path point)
EN1: J7.2 U1.2 | length 1070
  Top Layer w10: v1(2145.84,4531.2) 2146.55,4530.49 U1.2@2225.45,4530.49
  Layer 2 w10: J7.2@1595,5293.09 1595,5082.03 v1(2145.84,4531.2)
EN1_Rb: J23.2 U6.2 | length 1350.6
  Top Layer w10: v1(1820.12,1306.16) 1821.35,1307.39 1898.95,1307.39 U6.2@1898.95,1306.16
  Layer 2 w10: J23.2@1279.75,260 1279.75,290.38 1613.14,623.77 1613.14,1099.18 v1(1820.12,1306.16)
EN2: J8.2 U1.3 | length 951.6
  Top Layer w10: v1(2171.59,4505.73) 2172.42,4504.9 U1.3@2225.45,4504.9
  Layer 2 w10: J8.2@1943.77,5293.28 J8.2@1940.57,5296.49 1940.57,4860.18 2168.47,4632.27 2168.47,4508.84 v1(2171.59,4505.73) v1@2176.16,4501.16
EN2_Rb: J26.2 U6.3 | length 1142.1
  Top Layer w10: v1(1851.38,1284.76) 1855.57,1280.57 U6.3@1898.95,1280.57
  Layer 2 w10: J26.2@1689.47,260 1689.47,1124.6 1773.59,1208.72 1775.35,1208.72 v1(1851.38,1284.76)
EN3: J9.2 U3.2 | length 2060.3
  Top Layer w10: v1(2133.28,3768.14) U3.2@2208.44,3768.14
  Layer 2 w10: J9.2@239.68,3989.1 450.87,3777.91 1865.75,3777.91 1875.53,3768.14 v1(2133.28,3768.14)
EN4: J13.2 U3.3 | length 2281.9
  Top Layer w10: v1(2156.71,3741.56) 2157.69,3742.55 U3.3@2208.44,3742.55
  Layer 2 w10: J13.2@60.33,3992.49 346.83,3705.98 1876.34,3705.98 1911.92,3741.56 v1(2156.71,3741.56)
ERR1: J6.1 R5.2 TP3.1 U1.9 | length 1407.7
  Top Layer w10: R5.2@2451.59,4328.01 2451.59,4370.8 U1.9@2457.73,4376.95 ; TP3.1@2570.64,5193.15 2628.54,5251.04 J6.1@2628.54,5390
  Layer 2 w10: v1(2451.26,4328.01) 2528.88,4405.63 2528.88,5290.34 J6.1@2628.54,5390
ERR2: J6.2 R16.2 TP6.1 U3.9 | length 2359.5
  Top Layer w10: v1(2434.18,3496.8) 2440.72,3503.34 U3.9@2440.72,3614.6 U3.9@2444.58,3610.74 ; J6.2@2728.54,5390 2728.54,5245.25 TP6.1@2780.64,5193.15
  Layer 2 w10: v1(2434.18,3496.8) 2434.18,3914.73 2548.87,4029.41 2548.87,4393.64 2592.01,4436.78 2592.01,4572.32 2728.54,4708.85 J6.2@2728.54,5390
FB1: C4.2 R4.2 R11.2 U1.15 | length 202
  Top Layer w10: U1.15@2457.73,4530.49 2495.51,4530.49 R11.2@2528.88,4563.86 2514.67,4578.07 C4.2@2514.67,4617.55 R4.2@2572.09,4617.55
FB2: C3.2 R2.2 R3.2 R10.2 U1.13 | length 266.7
  Top Layer w10: U1.13@2457.73,4479.31 2505.26,4479.31 C3.2@2528.88,4455.69 R3.2@2570.36,4455.69 ; R10.2@2628.34,4407.46 2618.59,4407.46 R3.2@2570.36,4455.69 ; R2.2@2628.34,4475.76 2590.43,4475.76 R3.2@2570.36,4455.69
FB3: C17.2 R13.2 R15.2 R23.2 U3.15 | length 711.3
  Top Layer w10: v1(2368.69,3383.65) 2371.19,3386.15 R13.2@2371.19,3431.17 ; U3.15@2440.72,3768.14 2489.35,3768.14 2508.28,3787.08 v1(2508.28,3802.33) 2509.13,3803.18 2509.13,3853.92 C17.2@2507.47,3855.58 R15.2@2548.75,3855.58
  Layer 2 w10: v1(2368.69,3383.65) 2508.28,3523.24 v1(2508.28,3802.33)
FB4: C16.2 R14.2 R22.2 R24.2 U3.13 | length 383.6
  Top Layer w10: U3.13@2440.72,3716.96 2496.82,3716.96 C16.2@2513.56,3700.23 R14.2@2556.49,3700.23 2579.87,3700.23 2631.07,3751.43 2665.57,3751.43 R22.2@2678.54,3764.4 2699.64,3764.4 2748.75,3715.28 R24.2@2748.75,3693.53
GND: C2.2 C5.2 C6.2 C7.2 C8.1 C9.1 C10.1 C12.2 C13.2 C14.2 C15.2 C18.2 C19.2 C20.2 C21.2 C22.2 C23.1 C24.1 H10.1 H12.1 H14.1 H16.1 J1.2 J1.3 J1.4 J1.5 J2.1 J7.3 J8.3 J9.3 J10.1 J10.2 J11.2 J11.3 J11.4 J11.5 J13.1 J14.3 J15.3 J16.1 J16.2 J17.3 J18.3 R6.1 R7.1 R8.1 R9.1 R10.1 R11.1 R17.1 R18.1 R19.1 R20.1 R22.1 R23.1 TP4.1 TP7.1 U1.12 U1.17@2341.59,4466.51 U2.2 U3.12 U3.17@2324.58,3704.16 U4.2 U5.2 | length 2699.3
  Top Layer w10: C24.1@2018.95,3719.79 2036.82,3737.67 R19.1@2036.82,3769.79 ; J11.3@2139.66,4901.97 J11.2@2139.66,5001.97 J11.4@2239.66,5001.97 J11.5@2239.66,4901.97 2263.68,4877.95 C13.2@2263.68,4780.71 ; C14.2@2264.14,4649.57 2264.14,4565.61 v2(2288.44,4541.32) ; v3(2324.58,3704.16) 2337.38,3691.37 U3.12@2440.72,3691.37 ; C6.2@2327.56,4649.57 C6.2@2334.5,4656.51 ; C5.2@2334.82,4780.44 2359.22,4804.84 J1.3@2359.22,4901.97 J1.2@2359.22,5001.97 J1.4@2459.22,5001.97 J1.5@2459.22,4901.97 ; v3(2341.59,4466.51) 2354.39,4453.72 U1.12@2457.73,4453.72 ; R23.1@2546.81,3803.18 R23.1@2555.32,3803.18 ; U5.2@2646.32,3622.2 2646.32,3650.26 R17.1@2671.91,3675.85 2678.54,3682.48 R22.1@2678.54,3726.72
  Top Layer w30: C12.2@2257.92,4001.34 C15.2@2258.47,3918.88 ; 2292.62,4079.39 U3.17@2294.35,3781.6 ; 2300.8,4852.67 U1.17@2302.55,4535.79 ; C18.2@2326.87,3999.69 U3.17@2328.9,3780.95 ; 2332.86,4848.38 U1.17@2334.59,4550.6
  Top Layer w100: 2317.39,3584.73 U3.17@2317.39,3618.72 ; 2341.59,4357.72 v2(2341.59,4391.71)
  other v1: 2674.86,3675.85 2547.7,3800.67 3240,3922.91 2521.26,4312.06 2576.14,4312.2 2030.09,4416.51 1972.39,4419.11 2566.56,4563.86
  other v2: 2271.43,3629.36 2324.58,3629.36 2377.73,3629.36 2271.43,3666.76 2377.73,3666.76 2271.43,3704.16 2377.73,3704.16 2271.43,3741.56 2377.73,3741.56 2271.43,3778.97 2324.58,3778.97 2377.73,3778.97 2288.44,4391.71 2394.74,4391.71 2288.44,4429.11 2394.74,4429.11 2288.44,4466.51 2394.74,4466.51 2288.44,4503.91 2394.74,4503.91 2341.59,4541.32 2394.74,4541.32
  other v3: 2324.58,3666.76 2324.58,3741.56 2341.59,4429.11 2341.59,4503.91
GND2: C26.2 C29.2 C30.2 C31.2 C32.2 C33.2 C34.1 C35.1 H9.1 H11.1 H13.1 H15.1 J21.1 J21.2 J22.1 J22.2 J23.3 J24.3 J25.1 J26.3 J27.3 R30.1 R31.1 R32.1 R33.1 R34.1 R35.1 U6.12 U6.17@2015.09,1242.19 | length 593.1
  Top Layer w10: 1648.55,1307.59 1681.71,1307.59 C33.2@1693.62,1319.5 C35.1@1693.59,1262.19 ; R32.1@1699.77,1223.88 R32.1@1711.46,1212.19 ; C26.2@1950.97,1424.91 C26.2@1961.94,1413.93 ; v3(2015.09,1242.19) 2027.88,1229.39 U6.12@2131.23,1229.39 ; C29.2@2025.42,1424.91 C29.2@2025.74,1424.59 ; R33.1@2205.09,1100.69 2304.99,1100.69 v1(2307.94,1097.74) ; v1(2403.06,1110.53) 2406.9,1114.37 R34.1@2457.86,1114.37
  Top Layer w20: v2(1961.94,1316.99) C26.2@1961.94,1413.93
  Top Layer w30: C26.2@1950.97,1424.91 C29.2@2025.42,1424.91
  other v1: 2349.91,1164.3
  other v2: 1961.94,1167.38 2015.09,1167.38 2068.24,1167.38 1961.94,1204.79 2068.24,1204.79 1961.94,1242.19 2068.24,1242.19 1961.94,1279.59 2068.24,1279.59 2015.09,1316.99 2068.24,1316.99
  other v3: 2015.09,1204.79 2015.09,1279.59
ILIM1: R1.1 R9.2 R12.1 R21.1 TP1.1 U1.10 | length 2599.2
  Top Layer w10: U1.10@2457.73,4402.54 2497.06,4402.54 R9.2@2521.59,4378.01 2554.13,4345.47 2599.24,4345.47 2607.42,4337.29 v1(2643.34,4337.29) ; R12.1@2592.97,3263.45 2644.99,3263.45 2770.76,3389.23 v1(2770.76,3449.87) 2768.28,3452.35 R21.1@2715.21,3452.35 ; v1(2939.06,5150) 2939.06,5242.69 TP1.1@2989.51,5293.15
  Layer 2 w10: v1(2770.76,3449.87) 2770.76,3803.16 2643.34,3930.58 v1(2643.34,4337.29) 2643.34,4564.8 2939.06,4860.52 v1(2939.06,5150)
ILIM2: R6.2 TP2.1 U1.11 U2.3 | length 1453.4
  Top Layer w10: U1.11@2457.73,4428.13 2547.94,4428.13 2576.14,4399.93 R6.2@2576.14,4378.15 2681.71,4378.15 U2.3@2714.19,4345.66 2715.21,4346.69 v1(2715.21,4383.21) ; v1(3148.47,5150) 3148.47,5238.43 TP2.1@3203.19,5293.15
  Layer 2 w10: v1(2715.21,4383.21) 3148.47,4816.47 v1(3148.47,5150)
ILIM3: R20.2 TP5.1 U3.10 U4.3 | length 1289.1
  Top Layer w10: U3.10@2440.72,3640.19 2446.83,3634.09 2471.55,3634.09 2478.92,3626.72 2478.92,3462.15 U4.3@2509.77,3431.3 ; v1(2509.77,3471.05) U4.3@2509.77,3431.3 ; U4.3@2511.78,3429.28 U4.3@2509.77,3431.3 ; v1(2806.88,2770) 2876.88,2700 TP5.1@2876.88,2628.63
  Layer 2 w10: v1(2509.77,3471.05) 2806.88,3173.93 v1(2806.88,2770)
ILIM4: R17.2 TP8.1 U3.11 U5.3 | length 1483
  Top Layer w10: U3.11@2440.72,3665.78 2552.3,3665.78 ; v1(2554.13,3642.98) 2554.13,3663.95 2552.3,3665.78 ; R17.2@2605.96,3665.78 2552.3,3665.78 ; U5.3@2608.91,3622.2 R17.2@2608.91,3686.59 ; v1(3031.81,2770) 3031.81,2674.8 TP8.1@3076.88,2629.73
  Layer 2 w10: v1(2554.13,3642.98) 2554.13,3544.06 3031.81,3066.38 v1(3031.81,2770)
NetC1_1: C1.1 R1.2 U2.4 | length 247.8
  Top Layer w10: R1.2@2643.34,4274.3 2677.29,4274.3 U2.4@2714.19,4237.4 2768.32,4291.53 2847.17,4291.53 C1.1@2851.59,4295.95
NetC1_2: C1.2 R2.1 U2.1 | length 234.2
  Top Layer w10: R2.1@2691.34,4475.76 2788.99,4378.11 U2.1@2788.99,4345.66 2791.46,4343.19 C1.2@2851.59,4343.19
NetC11_1: C11.1 R12.2 U4.4 | length 133.1
  Top Layer w10: C11.1@2444.63,3323.03 2509.77,3323.03 U4.4@2511.78,3321.01 2529.97,3302.82 R12.2@2529.97,3263.45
